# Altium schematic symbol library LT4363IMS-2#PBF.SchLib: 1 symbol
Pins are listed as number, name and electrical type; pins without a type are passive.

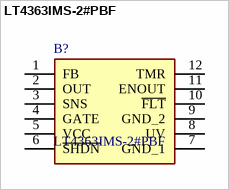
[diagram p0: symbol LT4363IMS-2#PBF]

## LT4363IMS-2#PBF
designator B?
High Voltage Surge Stopper with Current Limit; Manufacturer_Name: Analog Devices; Geometry.Height: 1.1mm
footprint SOP65P490X110-12N
pins: 1 FB, 2 OUT, 3 SNS, 4 GATE, 5 VCC, 6 ~{SHDN}, 7 GND_1, 8 UV, 9 GND_2, 10 ~{FLT}, 11 ENOUT, 12 TMR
